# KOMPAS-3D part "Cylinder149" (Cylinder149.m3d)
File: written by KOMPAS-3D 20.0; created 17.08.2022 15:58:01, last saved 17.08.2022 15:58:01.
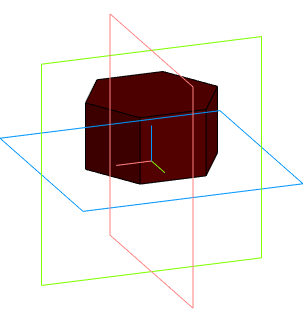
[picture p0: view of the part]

Document properties: Автор: artemsv220@gmail.com; Полное имя файла: \\192.168.2.25\новая общая папка\Медиа\Светильники\Кашпо\Кашпо и вазоны\DWG\Cylinder149.m3d

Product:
- Part/product: Cylinder149

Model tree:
1. Операция без истории:1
